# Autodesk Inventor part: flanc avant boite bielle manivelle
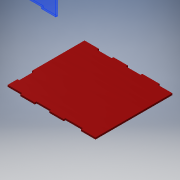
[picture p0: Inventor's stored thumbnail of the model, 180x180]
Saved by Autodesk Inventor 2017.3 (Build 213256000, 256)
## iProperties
Part Number: flanc avant boite bielle manivelle
Material: Générique
Document SubType Name: Modeling
Designer: ficho
Density: 1 g/cm^3
Appearance: Rouge
Author: ficho
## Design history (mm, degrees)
sketch "Esquisse1"
  geometry: L1 (0, 0)-(25, 0) reference; L2 (25, 0)-(25, 3) reference; L3 (0, 0)-(0, 3) reference; L4 (50, 0)-(75, 0) reference; L5 (75, 0)-(75, 3) reference; L6 (50, 0)-(50, 3) reference; L7 (28, 136)-(-7, 136) reference; L8 (-25, 3)-(-25, 136) reference; L9 (105, 136)-(105, 133); L10 (0, 3)-(-25, 3); L11 (25, 3)-(50, 3); L12 (75, 3)-(105, 3); L13 (75, 0)-(50, 0); L14 (25, 0)-(0, 0); L15 (25, 136)-(25, 133); L16 (25, 133)-(0, 133); L17 (0, 133)-(0, 136); L18 (75, 136)-(75, 133); L19 (75, 133)-(50, 133); L20 (50, 133)-(50, 136); L21 (-25, 136)-(0, 136); L22 (25, 136)-(50, 136); L23 (75, 136)-(105, 136); L24 (105, 133)-(130, 133); L25 (130, 133)-(130, 0); L26 (130, 0)-(105, 0); L27 (105, 0)-(105, 3); 2 further points
  constraints: 42 end point, 11 parallel, 4 perpendicular, 3 horizontal, 3 point on line, 1 collinear, 1 vertical, 2 other
  dimensions: "d0" = 25 distance of L15.end L16.end; "d1" = 3 distance of L15.start L15.end; "d2" = 25 distance of L18.end L19.end; "d3" = 3 distance of L18.start L18.end; "d4" = 25 distance between parallel lines of L20 L15 (= d0); "d5" = 25 distance between parallel lines of L17 L8 (= d4); "d8" = 25 distance of L25.end L26.end
extrude "Extrusion1" new body sketch "Esquisse1" distance "d6" = 3; taper "d7" = 0 deg
sketch "Esquisse2"
  geometry: L1 (-25, 136)-(-25, 3) reference; L2 (-25, 19.908)-(-22, 19.908); L3 (-22, 19.908)-(-22, 44.908); L4 (-22, 44.908)-(-25, 44.908); L5 (-25, 44.908)-(-25, 19.908); 1 further point
  constraints: 8 end point, 2 parallel, 1 horizontal, 1 perpendicular, 1 point on line
  dimensions: "d9" = 3 distance of L4.end L3.end; "d10" = 25 distance of L3.end L2.end
extrude "Extrusion2" cut sketch "Esquisse2" distance "d11" = 10; taper "d12" = 0 deg
node "Solide1"
node "Référence3"
